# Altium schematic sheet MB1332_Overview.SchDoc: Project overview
size A4; Date: Not used; ApprovedBy: Not used; CheckedBy: Not used; Author: Not used; CompanyName: STMicroelectronics; DrawnBy: Not used; Engineer: Not used; Organization: Not used; Address1: Not used; Address2: Not used; Address3: Not used; Address4: Not used; DocumentNumber: Not used; Revision: Not used; SheetNumber: 1; SheetTotal: 17
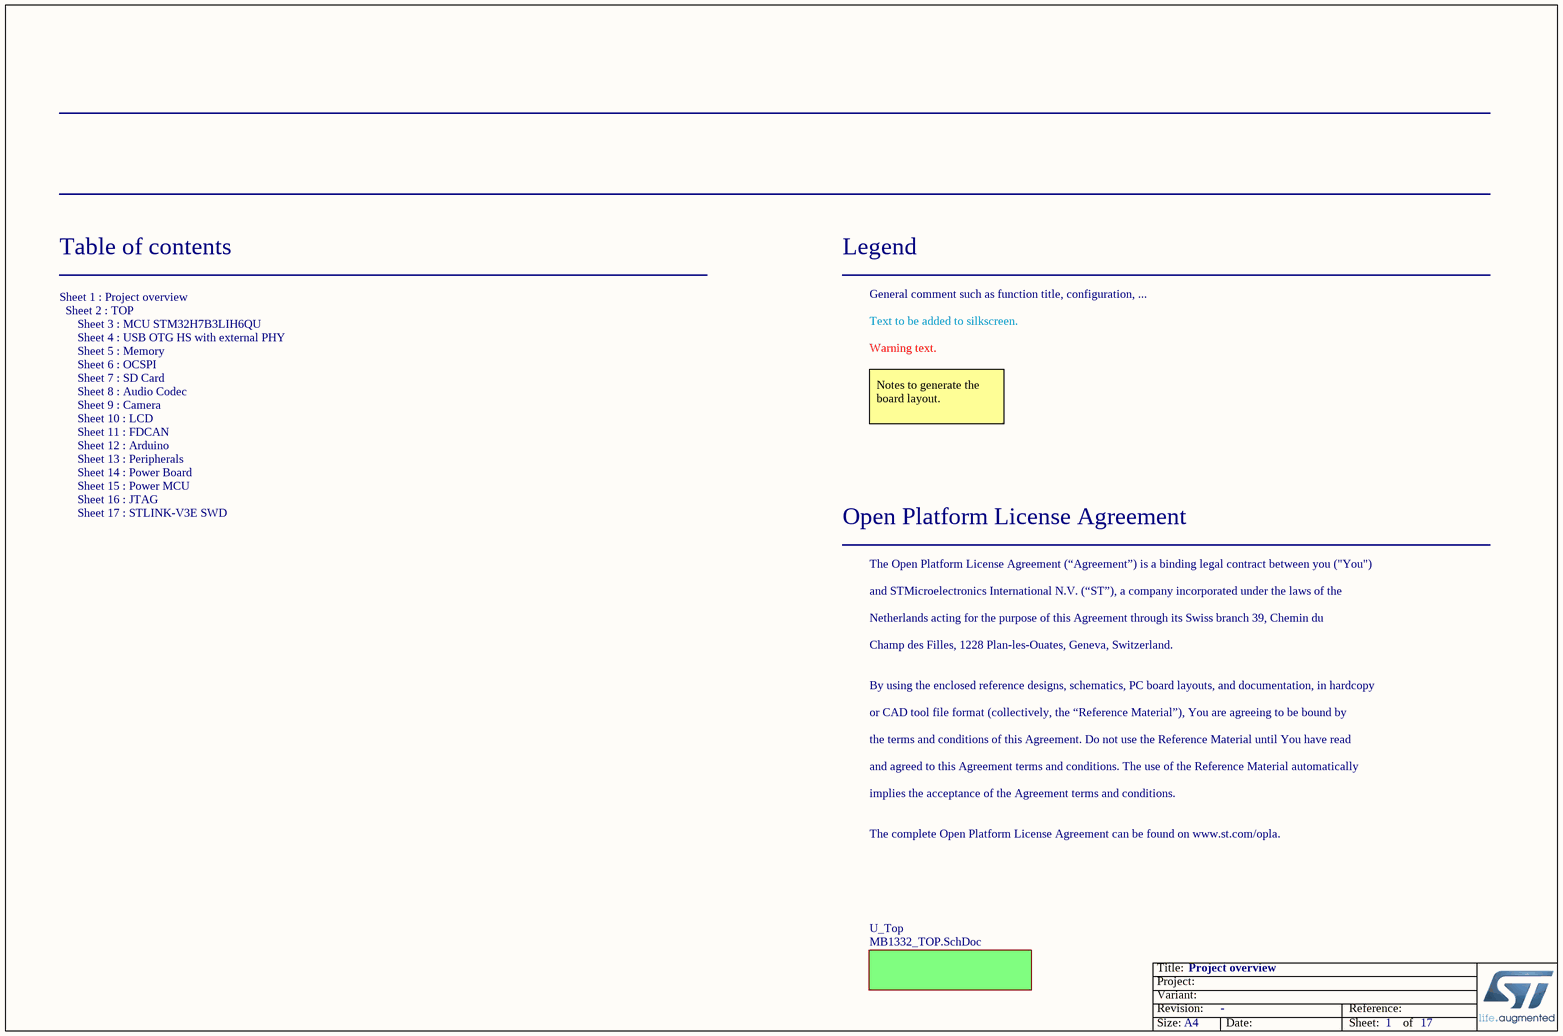
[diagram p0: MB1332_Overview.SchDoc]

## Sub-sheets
U_Top = MB1332_TOP.SchDoc: no entries

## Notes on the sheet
- Table of contents
- Legend
- General comment such as function title, configuration, ...
- Text to be added to silkscreen.
- Warning text.
- Notes to generate the board layout.
- Sheet 1 : Project overview
  Sheet 2 : TOP
  Sheet 3 : MCU STM32H7B3LIH6QU
  Sheet 4 : USB OTG HS with external PHY
  Sheet 5 : Memory
  Sheet 6 : OCSPI
  Sheet 7 : SD Card
  Sheet 8 : Audio Codec
  Sheet 9 : Camera
  Sheet 10 : LCD
  Sheet 11 : FDCAN
  Sheet 12 : Arduino
  Sheet 13 : Peripherals
  Sheet 14 : Power Board
  Sheet 15 : Power MCU
  Sheet 16 : JTAG
  Sheet 17 : STLINK-V3E SWD
- Open Platform License Agreement
- The Open Platform License Agreement (“Agreement”) is a binding legal contract between you ("You")
- and STMicroelectronics International N.V. (“ST”), a company incorporated under the laws of the
- Netherlands acting for the purpose of this Agreement through its Swiss branch 39, Chemin du
- Champ des Filles, 1228 Plan-les-Ouates, Geneva, Switzerland.
- By using the enclosed reference designs, schematics, PC board layouts, and documentation, in hardcopy
- or CAD tool file format (collectively, the “Reference Material”), You are agreeing to be bound by
- the terms and conditions of this Agreement. Do not use the Reference Material until You have read
- and agreed to this Agreement terms and conditions. The use of the Reference Material automatically
- implies the acceptance of the Agreement terms and conditions.
- The complete Open Platform License Agreement can be found on www.st.com/opla.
